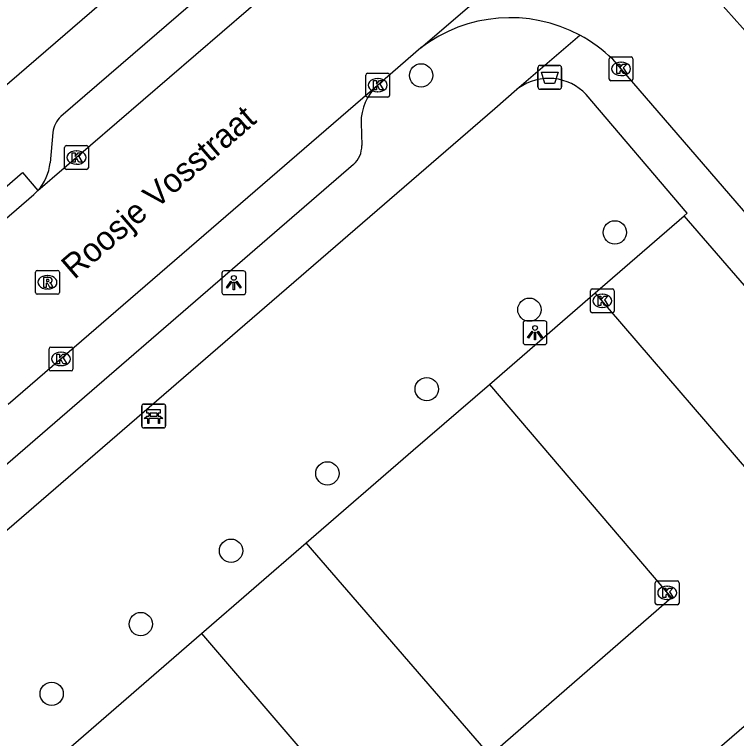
# Model space of a CAD drawing. Extents: x 160304 to 160954, y 383686 to 384161.
# Drawn here: x 160596.44 to 160626.77, y 384040.18 to 384070.59 of the extents above; entities that cross this region are included whole.
import ezdxf

# ---------------------------------------------------------------- set-up
doc = ezdxf.new("R2010")
doc.units = 0
for name, color, linetype in [('IMGEO_Afvalbak', 7, 'Continuous'), ('IMGEO_Bank', 7, 'Continuous'), ('IMGEO_Boom', 7, 'Continuous'), ('IMGEO_Kolk', 7, 'Continuous'), ('IMGEO_Lichtpunt', 7, 'Continuous'), ('IMGEO_Openbare_ruimte_label', 7, 'Continuous'), ('IMGEO_Parkeervlak_open', 7, 'Continuous'), ('IMGEO_Rijbaan_lokaal_open', 7, 'Continuous'), ('IMGEO_Rioolput', 7, 'Continuous'), ('IMGEO_Voetpad_open', 7, 'Continuous')]:
    doc.layers.add(name, color=color, linetype=linetype)

msp = doc.modelspace()

# ---------------------------------------------------------------- linework, layer by layer
at = {"layer": 'IMGEO_Afvalbak'}
for p, q in [((160618.529, 384068.447), (160619.319, 384068.447)), ((160619.319, 384068.447), (160618.529, 384068.447)), ((160618.429, 384067.547), (160618.429, 384068.347)), ((160618.429, 384068.347), (160618.429, 384067.547)), ((160619.419, 384068.347), (160619.419, 384067.547)), ((160619.419, 384067.547), (160619.419, 384068.347)), ((160619.319, 384067.447), (160618.529, 384067.447)), ((160618.529, 384067.447), (160619.319, 384067.447))]:
    msp.add_line(p, q, dxfattribs=at)
msp.add_lwpolyline([(160618.572, 384068.161), (160619.276, 384068.161), (160619.127, 384067.691), (160618.721, 384067.691), (160618.572, 384068.161)], dxfattribs=at)
for centre, start, end in [((160618.529, 384068.347), 90, 180), ((160618.529, 384068.347), 90, 180), ((160619.319, 384068.347), 0, 90), ((160619.319, 384068.347), 360, 90), ((160618.529, 384067.547), 180, 270), ((160618.529, 384067.547), 180, 270), ((160619.319, 384067.547), 270, 0), ((160619.319, 384067.547), 270, 0)]:
    msp.add_arc(centre, 0.1, start, end, dxfattribs=at)
at = {"layer": 'IMGEO_Bank'}
for p, q in [((160601.786, 384053.301), (160601.786, 384054.142)), ((160601.786, 384054.142), (160601.786, 384053.301)), ((160601.861, 384054.226), (160602.702, 384054.226)), ((160602.702, 384054.226), (160601.861, 384054.226)), ((160602.786, 384054.151), (160602.786, 384053.31)), ((160602.786, 384053.31), (160602.786, 384054.151)), ((160602.095, 384053.732), (160602.095, 384053.838)), ((160602.139, 384053.838), (160602.139, 384053.732)), ((160602.427, 384053.844), (160602.145, 384053.844)), ((160602.433, 384053.732), (160602.433, 384053.838)), ((160602.477, 384053.838), (160602.477, 384053.732)), ((160602.483, 384053.624), (160602.09, 384053.624)), ((160602.145, 384053.726), (160602.427, 384053.726)), ((160602.711, 384053.226), (160601.87, 384053.226)), ((160601.87, 384053.226), (160602.711, 384053.226))]:
    msp.add_line(p, q, dxfattribs=at)
for points in [[(160602.089, 384053.844), (160602.003, 384053.844), (160602.003, 384054.005), (160602.566, 384054.005), (160602.566, 384053.844), (160602.483, 384053.844)], [(160602.033, 384053.624), (160601.891, 384053.624), (160602.003, 384053.726), (160602.089, 384053.726)], [(160602.083, 384053.617), (160602.083, 384053.41), (160602.04, 384053.41), (160602.04, 384053.617)], [(160602.483, 384053.726), (160602.566, 384053.726), (160602.678, 384053.624), (160602.539, 384053.624)], [(160602.533, 384053.617), (160602.533, 384053.41), (160602.489, 384053.41), (160602.489, 384053.617)]]:
    msp.add_lwpolyline(points, dxfattribs=at)
for centre, radius, start, end in [((160601.864, 384054.148), 0.0779, 92.4484, 184.2845), ((160601.864, 384054.148), 0.0779, 92.4484, 184.2845), ((160602.708, 384054.148), 0.0779, 2.4484, 94.2845), ((160602.708, 384054.148), 0.0779, 2.4484, 94.2845), ((160602.088, 384053.837), 0.00671, 2.8957, 87.1043), ((160602.145, 384053.837), 0.00671, 92.8957, 177.1043), ((160602.427, 384053.837), 0.00671, 2.8957, 87.1043), ((160602.484, 384053.837), 0.00671, 92.8957, 177.1043), ((160602.033, 384053.617), 0.00671, 2.8957, 87.1043), ((160602.09, 384053.617), 0.00671, 92.8957, 177.1043), ((160602.088, 384053.733), 0.00671, 272.8957, 357.1043), ((160602.145, 384053.733), 0.00671, 182.8957, 267.1043), ((160602.427, 384053.733), 0.00671, 272.8957, 357.1043), ((160602.484, 384053.733), 0.00671, 182.8957, 267.1043), ((160602.482, 384053.617), 0.00671, 2.8957, 87.1043), ((160602.539, 384053.617), 0.00671, 92.8957, 177.1043), ((160601.864, 384053.304), 0.0779, 182.4484, 274.2845), ((160601.864, 384053.304), 0.0779, 182.4484, 274.2845), ((160602.708, 384053.304), 0.0779, 272.4484, 4.2845), ((160602.708, 384053.304), 0.0779, 272.4484, 4.2845)]:
    msp.add_arc(centre, radius, start, end, dxfattribs=at)
at = {"layer": 'IMGEO_Boom'}
for centre in [(160613.52, 384068.029), (160621.658, 384061.436), (160618.069, 384058.191), (160613.756, 384054.855), (160609.584, 384051.317), (160605.538, 384048.071), (160601.745, 384044.991), (160598.003, 384042.063)]:
    msp.add_circle(centre, 0.489, dxfattribs=at)
at = {"layer": 'IMGEO_Kolk'}
for p, q in [((160621.418, 384067.875), (160621.418, 384068.727)), ((160621.493, 384068.801), (160622.345, 384068.801)), ((160622.419, 384068.727), (160622.419, 384067.875)), ((160621.906, 384068.581), (160621.931, 384068.581)), ((160611.272, 384068.117), (160612.124, 384068.117)), ((160611.197, 384067.191), (160611.197, 384068.043)), ((160611.685, 384067.897), (160611.71, 384067.897)), ((160612.198, 384068.043), (160612.198, 384067.191)), ((160622.345, 384067.801), (160621.493, 384067.801)), ((160621.929, 384068.021), (160621.904, 384068.021)), ((160611.708, 384067.337), (160611.683, 384067.337)), ((160612.124, 384067.117), (160611.272, 384067.117)), ((160598.621, 384065.078), (160599.473, 384065.078)), ((160598.546, 384064.152), (160598.546, 384065.004)), ((160599.034, 384064.858), (160599.059, 384064.858)), ((160599.547, 384065.004), (160599.547, 384064.152)), ((160599.057, 384064.298), (160599.032, 384064.298)), ((160599.473, 384064.078), (160598.621, 384064.078)), ((160620.632, 384058.135), (160620.632, 384058.987)), ((160620.707, 384059.061), (160621.559, 384059.061)), ((160621.633, 384058.987), (160621.633, 384058.135)), ((160621.12, 384058.841), (160621.145, 384058.841)), ((160621.559, 384058.061), (160620.707, 384058.061)), ((160621.143, 384058.281), (160621.118, 384058.281)), ((160597.894, 384055.695), (160597.894, 384056.547)), ((160597.969, 384056.621), (160598.821, 384056.621)), ((160598.895, 384056.547), (160598.895, 384055.695)), ((160598.382, 384056.401), (160598.407, 384056.401)), ((160598.821, 384055.621), (160597.969, 384055.621)), ((160598.405, 384055.841), (160598.38, 384055.841)), ((160623.432, 384046.8), (160624.284, 384046.8)), ((160623.357, 384045.874), (160623.357, 384046.726)), ((160623.845, 384046.58), (160623.87, 384046.58)), ((160624.358, 384046.726), (160624.358, 384045.874)), ((160623.868, 384046.02), (160623.843, 384046.02)), ((160624.284, 384045.8), (160623.432, 384045.8))]:
    msp.add_line(p, q, dxfattribs=at)
for points in [[(160621.418, 384067.875), (160621.418, 384068.727)], [(160621.493, 384068.801), (160622.345, 384068.801)], [(160622.419, 384068.727), (160622.419, 384067.875)], [(160621.739, 384068.501), (160621.862, 384068.501), (160621.862, 384068.35), (160621.992, 384068.501), (160622.156, 384068.501), (160622.01, 384068.35), (160622.163, 384068.101), (160622.011, 384068.101), (160621.926, 384068.265), (160621.862, 384068.198), (160621.862, 384068.101), (160621.739, 384068.101), (160621.739, 384068.501)], [(160611.272, 384068.117), (160612.124, 384068.117)], [(160611.197, 384067.191), (160611.197, 384068.043)], [(160611.518, 384067.817), (160611.641, 384067.817), (160611.641, 384067.666), (160611.771, 384067.817), (160611.935, 384067.817), (160611.789, 384067.666), (160611.942, 384067.417), (160611.79, 384067.417), (160611.705, 384067.581), (160611.641, 384067.514), (160611.641, 384067.417), (160611.518, 384067.417), (160611.518, 384067.817)], [(160612.198, 384068.043), (160612.198, 384067.191)], [(160622.345, 384067.801), (160621.493, 384067.801)], [(160612.124, 384067.117), (160611.272, 384067.117)], [(160598.621, 384065.078), (160599.473, 384065.078)], [(160598.546, 384064.152), (160598.546, 384065.004)], [(160598.867, 384064.778), (160598.99, 384064.778), (160598.99, 384064.627), (160599.12, 384064.778), (160599.284, 384064.778), (160599.138, 384064.627), (160599.291, 384064.378), (160599.139, 384064.378), (160599.054, 384064.542), (160598.99, 384064.475), (160598.99, 384064.378), (160598.867, 384064.378), (160598.867, 384064.778)], [(160599.547, 384065.004), (160599.547, 384064.152)], [(160599.473, 384064.078), (160598.621, 384064.078)], [(160620.632, 384058.135), (160620.632, 384058.987)], [(160620.707, 384059.061), (160621.559, 384059.061)], [(160621.633, 384058.987), (160621.633, 384058.135)], [(160620.953, 384058.761), (160621.076, 384058.761), (160621.076, 384058.61), (160621.206, 384058.761), (160621.37, 384058.761), (160621.224, 384058.61), (160621.377, 384058.361), (160621.225, 384058.361), (160621.14, 384058.525), (160621.076, 384058.458), (160621.076, 384058.361), (160620.953, 384058.361), (160620.953, 384058.761)], [(160621.559, 384058.061), (160620.707, 384058.061)], [(160597.894, 384055.695), (160597.894, 384056.547)], [(160597.969, 384056.621), (160598.821, 384056.621)], [(160598.895, 384056.547), (160598.895, 384055.695)], [(160598.215, 384056.321), (160598.338, 384056.321), (160598.338, 384056.17), (160598.468, 384056.321), (160598.632, 384056.321), (160598.486, 384056.17), (160598.639, 384055.921), (160598.487, 384055.921), (160598.402, 384056.085), (160598.338, 384056.018), (160598.338, 384055.921), (160598.215, 384055.921), (160598.215, 384056.321)], [(160598.821, 384055.621), (160597.969, 384055.621)], [(160623.432, 384046.8), (160624.284, 384046.8)], [(160623.357, 384045.874), (160623.357, 384046.726)], [(160623.678, 384046.5), (160623.801, 384046.5), (160623.801, 384046.349), (160623.931, 384046.5), (160624.095, 384046.5), (160623.949, 384046.349), (160624.102, 384046.1), (160623.95, 384046.1), (160623.865, 384046.264), (160623.801, 384046.197), (160623.801, 384046.1), (160623.678, 384046.1), (160623.678, 384046.5)], [(160624.358, 384046.726), (160624.358, 384045.874)], [(160624.284, 384045.8), (160623.432, 384045.8)]]:
    msp.add_lwpolyline(points, dxfattribs=at)
for centre, start, end in [((160621.495, 384068.725), 91.552, 178.448), ((160621.495, 384068.725), 91.552, 178.448), ((160622.343, 384068.725), 1.552, 88.448), ((160622.343, 384068.725), 1.552, 88.448), ((160611.274, 384068.041), 91.552, 178.448), ((160611.274, 384068.041), 91.552, 178.448), ((160612.122, 384068.041), 1.552, 88.448), ((160612.122, 384068.041), 1.552, 88.448), ((160621.495, 384067.877), 181.552, 268.448), ((160621.495, 384067.877), 181.552, 268.448), ((160622.343, 384067.877), 271.552, 358.448), ((160622.343, 384067.877), 271.552, 358.448), ((160611.274, 384067.193), 181.552, 268.448), ((160611.274, 384067.193), 181.552, 268.448), ((160612.122, 384067.193), 271.552, 358.448), ((160612.122, 384067.193), 271.552, 358.448), ((160598.623, 384065.002), 91.552, 178.448), ((160598.623, 384065.002), 91.552, 178.448), ((160599.471, 384065.002), 1.552, 88.448), ((160599.471, 384065.002), 1.552, 88.448), ((160598.623, 384064.154), 181.552, 268.448), ((160598.623, 384064.154), 181.552, 268.448), ((160599.471, 384064.154), 271.552, 358.448), ((160599.471, 384064.154), 271.552, 358.448), ((160620.709, 384058.985), 91.552, 178.448), ((160620.709, 384058.985), 91.552, 178.448), ((160621.557, 384058.985), 1.552, 88.448), ((160621.557, 384058.985), 1.552, 88.448), ((160620.709, 384058.137), 181.552, 268.448), ((160620.709, 384058.137), 181.552, 268.448), ((160621.557, 384058.137), 271.552, 358.448), ((160621.557, 384058.137), 271.552, 358.448), ((160597.971, 384056.545), 91.552, 178.448), ((160597.971, 384056.545), 91.552, 178.448), ((160598.819, 384056.545), 1.552, 88.448), ((160598.819, 384056.545), 1.552, 88.448), ((160597.971, 384055.697), 181.552, 268.448), ((160597.971, 384055.697), 181.552, 268.448), ((160598.819, 384055.697), 271.552, 358.448), ((160598.819, 384055.697), 271.552, 358.448), ((160623.434, 384046.724), 91.552, 178.448), ((160623.434, 384046.724), 91.552, 178.448), ((160624.282, 384046.724), 1.552, 88.448), ((160624.282, 384046.724), 1.552, 88.448), ((160623.434, 384045.876), 181.552, 268.448), ((160623.434, 384045.876), 181.552, 268.448), ((160624.282, 384045.876), 271.552, 358.448), ((160624.282, 384045.876), 271.552, 358.448)]:
    msp.add_arc(centre, 0.0765, start, end, dxfattribs=at)
for centre, major_axis, ratio, start_param, end_param in [((160621.905, 384068.301), (-0.387, 0.002), 0.722429, 4.712389, 7.853982), ((160621.93, 384068.301), (-0.39, 0.002), 0.717154, 1.570796, 4.712389), ((160611.684, 384067.617), (-0.387, 0.002), 0.722429, 4.712389, 7.853982), ((160611.709, 384067.617), (-0.39, 0.002), 0.717154, 1.570796, 4.712389), ((160599.033, 384064.578), (-0.387, 0.002), 0.722429, 4.712389, 7.853982), ((160599.058, 384064.578), (-0.39, 0.002), 0.717154, 1.570796, 4.712389), ((160621.119, 384058.561), (-0.387, 0.002), 0.722429, 4.712389, 7.853982), ((160621.144, 384058.561), (-0.39, 0.002), 0.717154, 1.570796, 4.712389), ((160598.381, 384056.121), (-0.387, 0.002), 0.722429, 4.712389, 7.853982), ((160598.406, 384056.121), (-0.39, 0.002), 0.717154, 1.570796, 4.712389), ((160623.844, 384046.3), (-0.387, 0.002), 0.722429, 4.712389, 7.853982), ((160623.869, 384046.3), (-0.39, 0.002), 0.717154, 1.570796, 4.712389)]:
    msp.add_ellipse(centre, major_axis=major_axis, ratio=ratio, start_param=start_param, end_param=end_param, dxfattribs=at)
at = {"layer": 'IMGEO_Lichtpunt'}
for p, q in [((160605.156, 384059.726), (160605.156, 384058.919)), ((160605.156, 384059.726), (160605.156, 384058.919)), ((160606.058, 384059.821), (160605.25, 384059.821)), ((160606.058, 384059.821), (160605.25, 384059.821)), ((160606.152, 384058.919), (160606.152, 384059.726)), ((160606.152, 384058.919), (160606.152, 384059.726)), ((160605.25, 384058.825), (160606.058, 384058.825)), ((160605.25, 384058.825), (160606.058, 384058.825)), ((160617.807, 384057.625), (160617.807, 384056.818)), ((160617.807, 384057.625), (160617.807, 384056.818)), ((160618.709, 384057.72), (160617.901, 384057.72)), ((160618.709, 384057.72), (160617.901, 384057.72)), ((160618.803, 384056.818), (160618.803, 384057.625)), ((160618.803, 384056.818), (160618.803, 384057.625)), ((160617.901, 384056.724), (160618.709, 384056.724)), ((160617.901, 384056.724), (160618.709, 384056.724))]:
    msp.add_line(p, q, dxfattribs=at)
for points in [[(160605.53, 384059.39), (160605.569, 384059.362), (160605.381, 384059.1), (160605.343, 384059.127), (160605.53, 384059.39)], [(160605.632, 384059.342), (160605.679, 384059.342), (160605.679, 384059.02), (160605.632, 384059.02), (160605.632, 384059.342)], [(160605.742, 384059.362), (160605.78, 384059.389), (160605.967, 384059.127), (160605.928, 384059.099), (160605.742, 384059.362)], [(160618.181, 384057.289), (160618.22, 384057.261), (160618.032, 384056.999), (160617.994, 384057.026), (160618.181, 384057.289)], [(160618.283, 384057.241), (160618.33, 384057.241), (160618.33, 384056.919), (160618.283, 384056.919), (160618.283, 384057.241)], [(160618.393, 384057.261), (160618.431, 384057.288), (160618.618, 384057.026), (160618.579, 384056.998), (160618.393, 384057.261)]]:
    msp.add_lwpolyline(points, dxfattribs=at)
for centre in [(160605.655, 384059.524), (160618.306, 384057.423)]:
    msp.add_circle(centre, 0.0994, dxfattribs=at)
for centre, start, end in [((160605.25, 384059.726), 90, 180), ((160605.25, 384059.726), 90, 180), ((160606.058, 384059.726), 0, 90), ((160606.058, 384059.726), 0, 90), ((160605.25, 384058.919), 180, 270), ((160605.25, 384058.919), 180, 270), ((160606.058, 384058.919), 270, 0), ((160606.058, 384058.919), 270, 360), ((160617.901, 384057.625), 90, 180), ((160617.901, 384057.625), 90, 180), ((160618.709, 384057.625), 0, 90), ((160618.709, 384057.625), 0, 90), ((160617.901, 384056.818), 180, 270), ((160617.901, 384056.818), 180, 270), ((160618.709, 384056.818), 270, 0), ((160618.709, 384056.818), 270, 360)]:
    msp.add_arc(centre, 0.0946, start, end, dxfattribs=at)
at = {"layer": 'IMGEO_Parkeervlak_open'}
for points in [[(160620.836, 384058.904), (160624.569, 384062.136)], [(160608.699, 384048.399), (160613.194, 384052.29), (160616.388, 384055.055)], [(160596.702, 384038.014), (160604.299, 384044.59)]]:
    msp.add_lwpolyline(points, dxfattribs=at)
at = {"layer": 'IMGEO_Rijbaan_lokaal_open'}
for points in [[(160597.427, 384063.191), (160628.391, 384089.864)], [(160613.509, 384069.183), (160625.278, 384079.272)], [(160624.698, 384072.688), (160625.972, 384071.222), (160627.723, 384069.248)], [(160613.509, 384069.183), (160611.687, 384067.609)], [(160633.798, 384054.563), (160621.567, 384068.708)], [(160611.687, 384067.609), (160596.18, 384054.208)], [(160593.19, 384059.531), (160597.248, 384063.027), (160597.427, 384063.191)], [(160616.388, 384055.055), (160620.836, 384058.904)], [(160632.26, 384053.264), (160628.493, 384049.996), (160620.836, 384058.904)], [(160616.388, 384055.055), (160624.041, 384046.086), (160616.426, 384039.467), (160608.699, 384048.399)], [(160604.299, 384044.59), (160608.699, 384048.399)], [(160603.596, 384020.412), (160634.608, 384047.193)], [(160604.299, 384044.59), (160611.963, 384035.646), (160604.4, 384029.102), (160596.702, 384038.014)]]:
    msp.add_lwpolyline(points, dxfattribs=at)
for centre, radius, start, end in [((160617.262, 384064.262), 6.189, 61.856, 127.3301), ((160617.267, 384064.268), 6.181, 45.9145, 61.8687)]:
    msp.add_arc(centre, radius, start, end, dxfattribs=at)
at = {"layer": 'IMGEO_Rioolput'}
for p, q in [((160597.325, 384058.914), (160597.325, 384059.766)), ((160597.4, 384059.84), (160598.252, 384059.84)), ((160597.813, 384059.62), (160597.838, 384059.62)), ((160598.326, 384059.766), (160598.326, 384058.914)), ((160597.836, 384059.06), (160597.811, 384059.06)), ((160598.252, 384058.84), (160597.4, 384058.84))]:
    msp.add_line(p, q, dxfattribs=at)
for points in [[(160597.325, 384058.914), (160597.325, 384059.766)], [(160597.4, 384059.84), (160598.252, 384059.84)], [(160598.326, 384059.766), (160598.326, 384058.914)], [(160597.914, 384059.538), (160597.662, 384059.54), (160597.662, 384059.14)], [(160597.662, 384059.14), (160597.786, 384059.14), (160597.786, 384059.302), (160597.797, 384059.302)], [(160597.84, 384059.459), (160597.786, 384059.459), (160597.786, 384059.378)], [(160597.786, 384059.378), (160597.838, 384059.378)], [(160597.844, 384059.273), (160597.915, 384059.14), (160598.055, 384059.14), (160597.99, 384059.266)], [(160598.252, 384058.84), (160597.4, 384058.84)]]:
    msp.add_lwpolyline(points, dxfattribs=at)
for centre, radius, start, end in [((160597.402, 384059.764), 0.0765, 91.552, 178.448), ((160597.402, 384059.764), 0.0765, 91.552, 178.448), ((160598.25, 384059.764), 0.0765, 1.552, 88.448), ((160598.25, 384059.764), 0.0765, 1.552, 88.448), ((160597.796, 384059.249), 0.0533, 26.0293, 88.6989), ((160597.822, 384059.567), 0.19, 274.7715, 282.9687), ((160597.846, 384059.363), 0.0964, 77.0061, 93.1865), ((160597.86, 384059.42), 0.0378, 276.6634, 79.6772), ((160597.913, 384059.428), 0.109, 350.3612, 89.416), ((160597.911, 384059.428), 0.112, 277.5842, 350.9817), ((160597.895, 384059.213), 0.108, 29.5134, 73.7905), ((160597.402, 384058.916), 0.0765, 181.552, 268.448), ((160597.402, 384058.916), 0.0765, 181.552, 268.448), ((160598.25, 384058.916), 0.0765, 271.552, 358.448), ((160598.25, 384058.916), 0.0765, 271.552, 358.448)]:
    msp.add_arc(centre, radius, start, end, dxfattribs=at)
for centre, major_axis, ratio, start_param, end_param in [((160597.812, 384059.34), (-0.387, 0.002), 0.722429, 4.712389, 7.853982), ((160597.837, 384059.34), (-0.39, 0.002), 0.717154, 1.570796, 4.712389)]:
    msp.add_ellipse(centre, major_axis=major_axis, ratio=ratio, start_param=start_param, end_param=end_param, dxfattribs=at)
at = {"layer": 'IMGEO_Voetpad_open'}
for points in [[(160630.096, 384096.946), (160594.287, 384066.063)], [(160631.761, 384095.048), (160598.394, 384066.298)], [(160617.548, 384067.446), (160620.181, 384069.719)], [(160624.569, 384062.136), (160624.698, 384062.247), (160620.453, 384067.225), (160620.314, 384067.36), (160620.164, 384067.481), (160620.003, 384067.589), (160619.834, 384067.682), (160619.657, 384067.76), (160619.473, 384067.821), (160619.285, 384067.866), (160619.094, 384067.894), (160618.9, 384067.904), (160618.707, 384067.897), (160618.515, 384067.873), (160618.424, 384067.853), (160618.326, 384067.832), (160618.142, 384067.775), (160617.963, 384067.701), (160617.792, 384067.611), (160617.629, 384067.506), (160617.548, 384067.446)], [(160588.993, 384042.795), (160607.555, 384058.819), (160616.616, 384066.641), (160617.548, 384067.446)], [(160610.997, 384066.031), (160611.028, 384065.08)], [(160598.051, 384065.632), (160597.934, 384064.359)], [(160610.683, 384064.29), (160592.733, 384048.779)], [(160593.19, 384059.531), (160592.537, 384060.288), (160596.775, 384063.949), (160597.427, 384063.191)], [(160632.26, 384053.264), (160624.569, 384062.136)]]:
    msp.add_lwpolyline(points, dxfattribs=at)
for centre, radius, start, end in [((160613.089, 384066.056), 2.092, 132.0807, 180.6834), ((160599.051, 384065.538), 1.004, 130.8562, 174.6455), ((160610.028, 384065.046), 1, 310.884, 1.9333), ((160595.923, 384064.538), 2.019, 318.1536, 354.9174)]:
    msp.add_arc(centre, radius, start, end, dxfattribs=at)

# ---------------------------------------------------------------- texts
at = {"layer": 'IMGEO_Openbare_ruimte_label'}
msp.add_text('Roosje Vosstraat', height=1, rotation=40.8249, dxfattribs=at).set_placement((160598.957, 384059.431))

doc.saveas('drawing.dxf')
